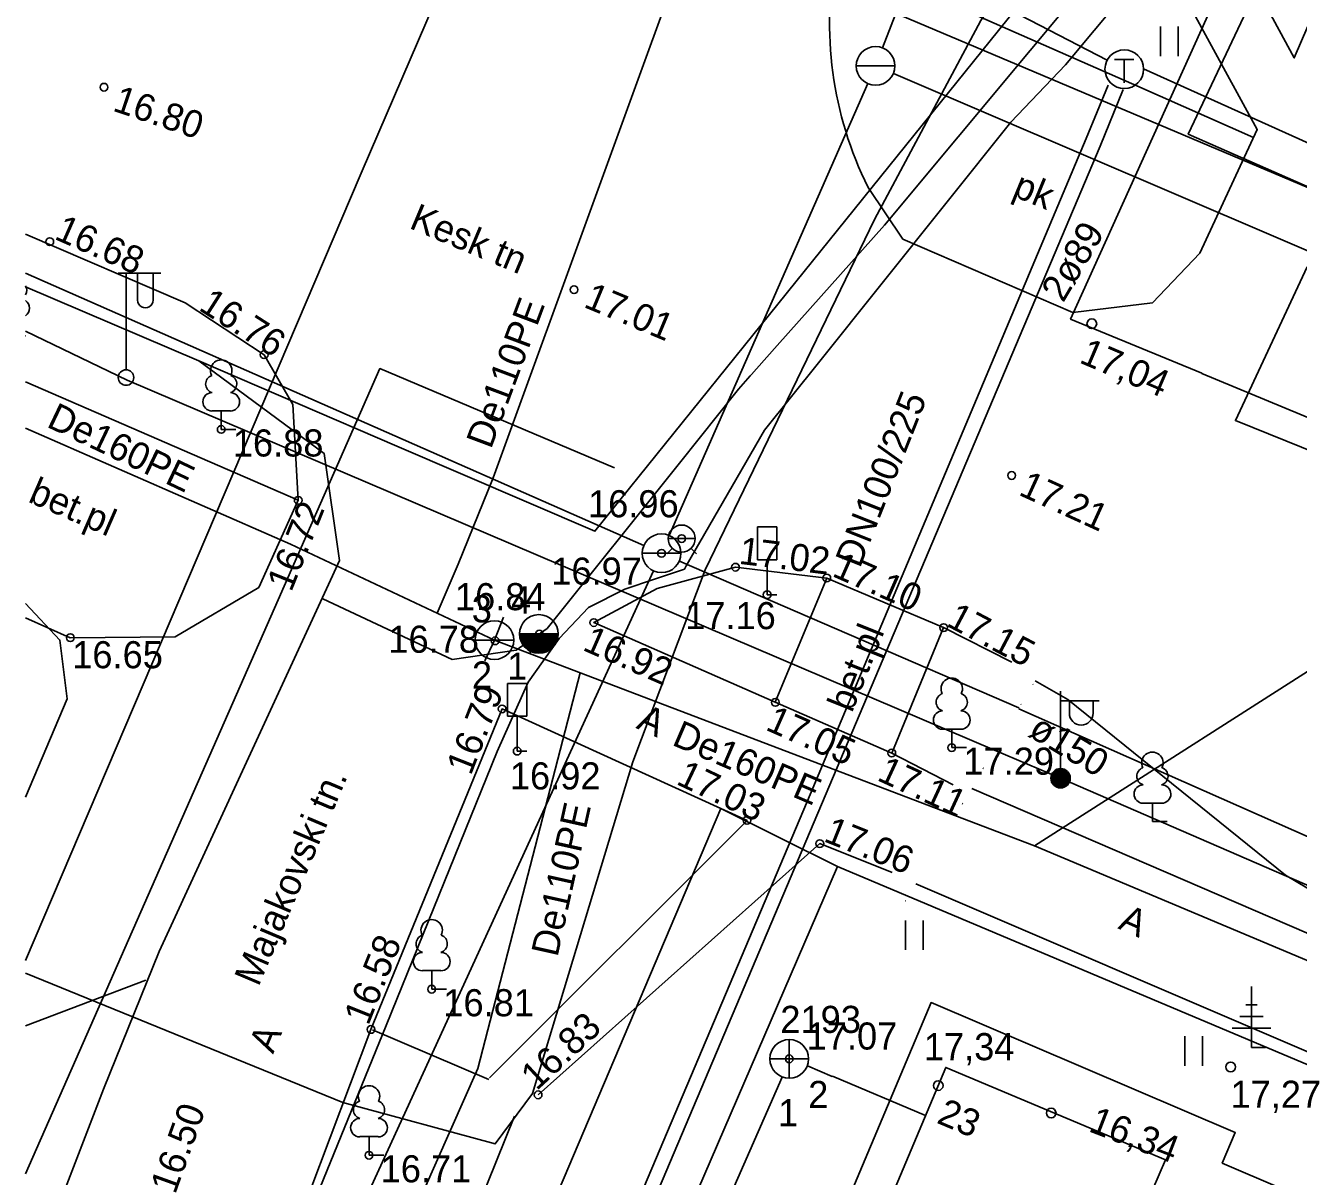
# Model space of a CAD drawing. Extents: x 713497 to 713863, y 6590062 to 6590327.
# Drawn here: x 713496.86 to 713529.76, y 6590263.86 to 6590293.59 of the extents above; entities that cross this region are included whole.
import ezdxf

# ---------------------------------------------------------------- set-up
doc = ezdxf.new("R2010")
doc.units = 0
for name, color, linetype in [('HALJASTUS', 7, 'Continuous'), ('HOONE', 7, 'Continuous'), ('KKAEV', 7, 'Continuous'), ('KORGUS', 7, 'Continuous'), ('KPKAABEL', 7, 'Continuous'), ('KTRASS', 7, 'Continuous'), ('LIIKLUS', 7, 'Continuous'), ('MPKAABEL', 7, 'Continuous'), ('POST', 7, 'Continuous'), ('PUU', 7, 'Continuous'), ('SIKAEV', 7, 'Continuous'), ('SITRASS', 7, 'Continuous'), ('TEE', 7, 'Continuous'), ('TKAEV', 7, 'Continuous'), ('TORU NR', 7, 'Continuous'), ('TTRASS', 7, 'Continuous'), ('VKAEV', 7, 'Continuous'), ('VTRASS', 7, 'Continuous'), ('Слой 1', 7, 'Continuous')]:
    doc.layers.add(name, color=color, linetype=linetype)

msp = doc.modelspace()

# ---------------------------------------------------------------- linework, layer by layer
at = {"layer": 'HALJASTUS'}
for p, q in [((713526.192, 6590293.566), (713526.192, 6590292.805)), ((713526.647, 6590293.566), (713526.647, 6590292.805)), ((713519.603, 6590270.476), (713519.603, 6590269.715)), ((713520.058, 6590270.476), (713520.058, 6590269.715)), ((713526.826, 6590267.486), (713526.826, 6590266.724)), ((713527.281, 6590267.486), (713527.281, 6590266.724))]:
    msp.add_line(p, q, dxfattribs=at)
msp.add_lwpolyline([(713521.623, 6590274.399), (713521.607, 6590274.406)], dxfattribs=at)
at = {"layer": 'HOONE'}
for points in [[(713505.559, 6590289.839), (713515.06, 6590311.86), (713519.629, 6590322.555)], [(713527.264, 6590284.61), (713523.87, 6590286.01), (713535.98, 6590312.79)], [(713496.861, 6590269.441), (713505.51, 6590289.72), (713505.559, 6590289.839)], [(713527.261, 6590284.603), (713571.838, 6590266.115), (713573.888, 6590266.247), (713614.395, 6590248.483), (713630.517, 6590241.151), (713667.174, 6590224.027), (713666.91, 6590213.67), (713710.13, 6590192.26), (713734.713, 6590179.152)], [(713560.928, 6590245.865), (713562.226, 6590248.956), (713556.488, 6590251.366), (713556.171, 6590250.61), (713545.867, 6590255.029), (713546.422, 6590256.351), (713536.953, 6590260.398), (713536.402, 6590259.089), (713526, 6590263.535), (713526.322, 6590264.289), (713520.645, 6590266.681), (713517.107, 6590258.276)]]:
    msp.add_lwpolyline(points, dxfattribs=at)
at = {"layer": 'KKAEV'}
for p, q in [((713516.6, 6590266.4), (713516.6, 6590267.4)), ((713516.1, 6590266.9), (713517.1, 6590266.9))]:
    msp.add_line(p, q, dxfattribs=at)
msp.add_circle((713516.6, 6590266.9), 0.5, dxfattribs=at)
at = {"layer": 'KORGUS'}
for centre, radius in [((713498.89, 6590292), 0.1), ((713497.49, 6590288.01), 0.1), ((713511.04, 6590286.77), 0.1), ((713524.42, 6590285.89), 0.125), ((713503.03, 6590285.09), 0.1), ((713501.92, 6590283.16), 0.1), ((713522.35, 6590281.97), 0.1), ((713503.91, 6590281.33), 0.1), ((713513.82, 6590280.34), 0.1), ((713513.3, 6590279.96), 0.1), ((713515.21, 6590279.6), 0.1), ((713517.57, 6590279.32), 0.1), ((713516.03, 6590278.89), 0.1), ((713511.55, 6590278.17), 0.1), ((713520.59, 6590278.04), 0.1), ((713498.02, 6590277.78), 0.1), ((713510.14, 6590277.87), 0.1), ((713509, 6590277.7), 0.1), ((713516.24, 6590276.11), 0.1), ((713509.18, 6590275.94), 0.1), ((713509.57, 6590274.85), 0.1), ((713519.25, 6590274.8), 0.1), ((713520.8, 6590274.94), 0.1), ((713515.51, 6590273.06), 0.1), ((713517.39, 6590272.46), 0.1), ((713507.36, 6590268.7), 0.1), ((713505.79, 6590267.66), 0.1), ((713516.6, 6590266.9), 0.1), ((713528.01, 6590266.69), 0.125), ((713520.45, 6590266.21), 0.125), ((713510.11, 6590265.97), 0.1), ((713523.37, 6590265.5), 0.125), ((713505.74, 6590264.41), 0.1)]:
    msp.add_circle(centre, radius, dxfattribs=at)
at = {"layer": 'KPKAABEL'}
msp.add_lwpolyline([(713529.988, 6590287.362), (713528.13, 6590283.39), (713562.908, 6590269.342), (713609.57, 6590248.393), (713642.834, 6590233.164), (713665.543, 6590222.669), (713703.801, 6590203.145), (713710.007, 6590200.019), (713735.256, 6590187.298), (713757.247, 6590176.218), (713786.95, 6590160.25), (713778.485, 6590144.103)], dxfattribs=at)
at = {"layer": 'KTRASS'}
for p, q in [((713517.711, 6590266.44), (713517.07, 6590266.72)), ((713516.42, 6590266.43), (713507.63, 6590246.48))]:
    msp.add_line(p, q, dxfattribs=at)
msp.add_lwpolyline([(713517.716, 6590266.452), (713520.122, 6590265.44)], dxfattribs=at)
at = {"layer": 'LIIKLUS'}
for p, q in [((713515.78, 6590280.64), (713515.78, 6590279.79)), ((713516.28, 6590280.64), (713515.78, 6590280.64)), ((713516.28, 6590280.64), (713516.28, 6590279.79)), ((713516.28, 6590279.79), (713515.78, 6590279.79)), ((713516.03, 6590279.79), (713516.03, 6590278.89)), ((713516.28, 6590278.89), (713516.03, 6590278.89)), ((713509.32, 6590276.6), (713509.32, 6590275.75)), ((713509.82, 6590276.6), (713509.32, 6590276.6)), ((713509.82, 6590276.6), (713509.82, 6590275.75)), ((713509.82, 6590275.75), (713509.32, 6590275.75)), ((713509.57, 6590275.75), (713509.57, 6590274.85)), ((713509.82, 6590274.85), (713509.57, 6590274.85))]:
    msp.add_line(p, q, dxfattribs=at)
at = {"layer": 'MPKAABEL'}
for points in [[(713556.424, 6590327.391), (713556.223, 6590326.664), (713552.132, 6590327.245), (713549.78, 6590326.91), (713545.79, 6590321.14), (713541.662, 6590317.664), (713538.182, 6590313.186), (713528.61, 6590303.11), (713525.635, 6590299.613), (713521.549, 6590293.725), (713518.804, 6590288.58), (713514.43, 6590279.53), (713512.558, 6590274.575), (713509.964, 6590266.002), (713509.002, 6590264.701), (713505.064, 6590265.776), (713496.861, 6590269.111)], [(713531.89, 6590304.492), (713530.4, 6590302.03), (713519.06, 6590288.44), (713516.291, 6590285.326)], [(713515.66, 6590285.591), (713524.88, 6590297.03), (713531.868, 6590304.442)], [(713517.352, 6590284.879), (713522.33, 6590291.1), (713523.74, 6590292.58), (713528.97, 6590298.85), (713530.064, 6590300.386)], [(713496.861, 6590286.847), (713501.34, 6590284.93), (713506.46, 6590282.73), (713511.58, 6590280.53), (713515.657, 6590285.592)], [(713521.905, 6590274.877), (713499.491, 6590284.435), (713496.861, 6590285.699)], [(713516.291, 6590285.326), (713515.29, 6590284.2), (713513.76, 6590282.29), (713510.34, 6590278.02), (713509.54, 6590277.46), (713507.89, 6590277.22), (713504.55, 6590278.78)], [(713496.861, 6590260.884), (713496.98, 6590261.19), (713498.88, 6590266.12), (713500.32, 6590269.67), (713502.73, 6590274.9), (713504.8, 6590279.38), (713504.98, 6590279.77), (713504.58, 6590282.54), (713501.34, 6590284.93)], [(713517.352, 6590284.879), (713515.96, 6590283.14), (713513.94, 6590279.64), (713513.89, 6590279.55), (713513.12, 6590279.29), (713512.35, 6590279.03), (713511.41, 6590278.56), (713510.65, 6590277.76), (713509.85, 6590276.63), (713509.05, 6590274.84), (713506.18, 6590267.76), (713501.78, 6590256.97), (713499.96, 6590252.48), (713497.24, 6590245.7), (713496.861, 6590244.767)], [(713496.861, 6590263.928), (713503.3, 6590278.54), (713506.02, 6590284.73), (713512.08, 6590282.17)], [(713504.55, 6590278.78), (713507.89, 6590277.22), (713509.54, 6590277.46), (713510.34, 6590278.02), (713513.76, 6590282.29), (713515.29, 6590284.2), (713515.59, 6590284.54)], [(713522.597, 6590276.054), (713522.584, 6590276.059)], [(713649.332, 6590187.338), (713640.094, 6590185.585), (713635.77, 6590206.95), (713632.04, 6590224.25), (713630.57, 6590226.81), (713628.65, 6590228.67), (713627.42, 6590229.49), (713598.73, 6590243.21), (713583.058, 6590248.245), (713565.046, 6590256.189), (713523.612, 6590274.149), (713521.905, 6590274.877)], [(713496.861, 6590267.757), (713499.97, 6590268.93)]]:
    msp.add_lwpolyline(points, dxfattribs=at)
at = {"layer": 'POST'}
for p, q in [((713499.26, 6590287.2), (713500.36, 6590287.2)), ((713499.46, 6590287.2), (713499.46, 6590284.7)), ((713499.76, 6590287.2), (713499.76, 6590286.5)), ((713500.16, 6590287.2), (713500.16, 6590286.5)), ((713523.612, 6590274.399), (713523.612, 6590276.399)), ((713523.612, 6590276.149), (713524.612, 6590276.149)), ((713523.839, 6590275.828), (713523.839, 6590276.149)), ((713524.452, 6590275.828), (713524.452, 6590276.149))]:
    msp.add_line(p, q, dxfattribs=at)
for centre, radius in [((713499.46, 6590284.5), 0.2), ((713523.612, 6590274.149), 0.25), ((713523.612, 6590274.149), 0.225), ((713523.612, 6590274.149), 0.2), ((713523.612, 6590274.149), 0.175), ((713523.612, 6590274.149), 0.15), ((713523.612, 6590274.149), 0.125), ((713523.612, 6590274.149), 0.1), ((713523.612, 6590274.149), 0.075), ((713523.612, 6590274.149), 0.05), ((713523.612, 6590274.149), 0.025)]:
    msp.add_circle(centre, radius, dxfattribs=at)
for centre, radius, start, end in [((713499.96, 6590286.5), 0.2, 179.9393, 0.0607), ((713524.145, 6590275.828), 0.306, 180, 0)]:
    msp.add_arc(centre, radius, start, end, dxfattribs=at)
at = {"layer": 'PUU'}
for p, q in [((713496.87, 6590285.58), (713496.861, 6590285.58)), ((713502.16, 6590283.64), (713501.68, 6590283.64)), ((713501.92, 6590283.16), (713501.92, 6590283.64)), ((713502.3, 6590283.16), (713501.92, 6590283.16)), ((713521.04, 6590275.42), (713520.56, 6590275.42)), ((713520.8, 6590274.94), (713520.8, 6590275.42)), ((713521.18, 6590274.94), (713520.8, 6590274.94)), ((713526.226, 6590273.503), (713525.746, 6590273.503)), ((713525.986, 6590273.028), (713525.986, 6590273.503)), ((713526.366, 6590273.028), (713525.986, 6590273.028)), ((713507.6, 6590269.18), (713507.12, 6590269.18)), ((713507.36, 6590268.7), (713507.36, 6590269.18)), ((713507.74, 6590268.7), (713507.36, 6590268.7)), ((713528.547, 6590267.193), (713528.547, 6590268.768)), ((713528.697, 6590268.293), (713528.397, 6590268.293)), ((713528.847, 6590267.993), (713528.247, 6590267.993)), ((713529.047, 6590267.693), (713528.047, 6590267.693)), ((713528.907, 6590267.193), (713528.547, 6590267.193)), ((713505.98, 6590264.89), (713505.5, 6590264.89)), ((713505.74, 6590264.41), (713505.74, 6590264.89)), ((713506.12, 6590264.41), (713505.74, 6590264.41))]:
    msp.add_line(p, q, dxfattribs=at)
for centre, radius, start, end in [((713496.66, 6590286.753), 0.233, 329.9101, 30.0899), ((713496.727, 6590286.292), 0.238, 304.2921, 55.7079), ((713501.92, 6590284.68), 0.277, 332.5799, 207.4201), ((713501.75, 6590284.333), 0.233, 109.0217, 253.1415), ((713502.09, 6590284.333), 0.233, 286.8508, 70.9859), ((713501.683, 6590283.872), 0.238, 90.0016, 269.3953), ((713502.157, 6590283.872), 0.238, 270.6047, 89.9984), ((713520.8, 6590276.46), 0.277, 332.5799, 207.4201), ((713520.63, 6590276.113), 0.233, 109.0217, 253.1415), ((713520.97, 6590276.113), 0.233, 286.8508, 70.9859), ((713520.563, 6590275.652), 0.238, 90.0016, 269.3953), ((713521.037, 6590275.652), 0.238, 270.6047, 89.9984), ((713525.986, 6590274.548), 0.277, 332.5799, 207.4201), ((713525.816, 6590274.201), 0.233, 109.0217, 253.1415), ((713526.157, 6590274.201), 0.233, 286.8508, 70.9859), ((713525.749, 6590273.741), 0.238, 90.0016, 269.3953), ((713526.224, 6590273.741), 0.238, 270.6047, 89.9984), ((713507.36, 6590270.22), 0.277, 332.5799, 207.4201), ((713507.19, 6590269.873), 0.233, 109.0217, 253.1415), ((713507.53, 6590269.873), 0.233, 286.8508, 70.9859), ((713507.123, 6590269.412), 0.238, 90.0016, 269.3953), ((713507.597, 6590269.412), 0.238, 270.6047, 89.9984), ((713505.74, 6590265.93), 0.277, 332.5799, 207.4201), ((713505.57, 6590265.583), 0.233, 109.0217, 253.1415), ((713505.91, 6590265.583), 0.233, 286.8508, 70.9859), ((713505.503, 6590265.122), 0.238, 90.0016, 269.3953), ((713505.977, 6590265.122), 0.238, 270.6047, 89.9984)]:
    msp.add_arc(centre, radius, start, end, dxfattribs=at)
at = {"layer": 'SITRASS'}
for points in [[(713496.861, 6590303.284), (713500.921, 6590301.592), (713518.63, 6590294.21), (713525.943, 6590291.121), (713547.87, 6590281.86), (713577.05, 6590269.06)], [(713496.861, 6590273.664), (713497.94, 6590276.2), (713497.75, 6590277.72), (713496.861, 6590278.662)]]:
    msp.add_lwpolyline(points, dxfattribs=at)
at = {"layer": 'TEE'}
for p, q in [((713516.24, 6590276.11), (713517.57, 6590279.32)), ((713519.25, 6590274.8), (713520.59, 6590278.04)), ((713505.83, 6590267.65), (713508.84, 6590266.37)), ((713509.5, 6590265.42), (713505.67, 6590255.93))]:
    msp.add_line(p, q, dxfattribs=at)
for points in [[(713573.49, 6590310.58), (713571.43, 6590310.51), (713568.73, 6590310.13), (713566.75, 6590309.6), (713565.2, 6590309.33), (713563.34, 6590309.28), (713559.47, 6590309.2), (713550.571, 6590309.122), (713547.007, 6590308.859), (713543.266, 6590308.267), (713539.684, 6590306.737), (713533.203, 6590301.01), (713529.652, 6590292.758), (713524.443, 6590302.359), (713528.272, 6590311.829), (713529.607, 6590315.209), (713534.577, 6590327.391)], [(713528.697, 6590290.905), (713523.614, 6590300.222), (713521.391, 6590293.979)], [(713517.839, 6590295.448), (713524.737, 6590292.406), (713525.581, 6590292.034), (713528.602, 6590290.701), (713528.697, 6590290.905), (713527.21, 6590287.717), (713525.99, 6590286.43), (713523.928, 6590286.179), (713519.539, 6590288.076), (713518.637, 6590289.412)], [(713496.861, 6590288.208), (713500.99, 6590286.43), (713503.03, 6590285.09), (713503.77, 6590283.8), (713503.91, 6590281.33), (713502.89, 6590279.08), (713500.73, 6590277.8), (713498.02, 6590277.78), (713496.861, 6590278.291)], [(713503.91, 6590281.33), (713496.861, 6590284.391)], [(713520.84, 6590273.98), (713519.25, 6590274.8), (713516.24, 6590276.11), (713511.55, 6590278.17), (713513.19, 6590279.05), (713515.21, 6590279.6), (713517.57, 6590279.32), (713520.59, 6590278.04), (713522.35, 6590277.15)], [(713522.892, 6590276.579), (713522.903, 6590276.574)], [(713567.652, 6590257.496), (713558.117, 6590259.202), (713555.243, 6590260.095), (713531.713, 6590270.286), (713529.422, 6590271.644), (713523.797, 6590276.181), (713522.955, 6590276.663)], [(713503.16, 6590260.68), (713505.79, 6590267.66), (713509.18, 6590275.94), (713515.51, 6590273.06), (713508.85, 6590266.41)], [(713521.322, 6590273.886), (713531.345, 6590269.56)], [(713521.087, 6590273.488), (713521.069, 6590273.496)], [(713510.11, 6590265.97), (713517.39, 6590272.46), (713519.26, 6590271.71)], [(713519.87, 6590271.419), (713539.627, 6590262.954)], [(713519.614, 6590270.982), (713519.607, 6590270.985)], [(713536.914, 6590260.306), (713527.79, 6590264.206), (713528.127, 6590264.994), (713520.265, 6590268.354), (713516.169, 6590258.625)]]:
    msp.add_lwpolyline(points, dxfattribs=at)
msp.add_arc((713527.16, 6590293.653), 9.519, 168.9353, 206.4518, dxfattribs=at)
at = {"layer": 'TKAEV'}
for p, q in [((713525.009, 6590292.716), (713525.509, 6590292.716)), ((713525.259, 6590292.116), (713525.259, 6590292.716))]:
    msp.add_line(p, q, dxfattribs=at)
msp.add_circle((713525.259, 6590292.466), 0.5, dxfattribs=at)
at = {"layer": 'TTRASS'}
for points in [[(713519.57, 6590295.42), (713524.815, 6590292.696)], [(713579.86, 6590268.18), (713569.16, 6590273.06), (713552.4, 6590280.47), (713525.759, 6590292.472)], [(713524.838, 6590292.055), (713524.274, 6590290.678), (713517.074, 6590273.563), (713509.525, 6590255.749), (713509.26, 6590255.635), (713504.886, 6590257.539), (713504.59, 6590257.406), (713499.908, 6590246.416), (713496.861, 6590238.236)], [(713525.234, 6590291.937), (713524.637, 6590290.479), (713517.341, 6590273.249), (713509.7, 6590255.207), (713509.387, 6590255.185), (713505.154, 6590257.086), (713504.889, 6590256.981), (713500.184, 6590245.949), (713496.861, 6590237.277)]]:
    msp.add_lwpolyline(points, dxfattribs=at)
at = {"layer": 'VKAEV'}
for p, q in [((713518.331, 6590292.55), (713519.331, 6590292.55)), ((713513.47, 6590280.34), (713514.17, 6590280.34)), ((713512.8, 6590279.96), (713513.8, 6590279.96)), ((713513.58, 6590280.09), (713513.44, 6590279.95)), ((713514.06, 6590280.09), (713514.2, 6590279.95)), ((713509.629, 6590277.876), (713510.629, 6590277.876)), ((713508.482, 6590277.717), (713509.482, 6590277.717))]:
    msp.add_line(p, q, dxfattribs=at)
for centre, radius in [((713518.831, 6590292.55), 0.5), ((713513.3, 6590279.96), 0.5), ((713513.82, 6590280.34), 0.35), ((713508.982, 6590277.717), 0.5), ((713510.129, 6590277.876), 0.5)]:
    msp.add_circle(centre, radius, dxfattribs=at)
for radius in [0.483, 0.468, 0.45, 0.435, 0.418, 0.403, 0.386, 0.371, 0.354, 0.339, 0.321, 0.306, 0.289, 0.274, 0.257, 0.242, 0.224, 0.209, 0.192, 0.177, 0.16, 0.145, 0.127, 0.112, 0.0951, 0.0801, 0.0628, 0.0478, 0.0328, 0.0178]:
    msp.add_arc((713510.129, 6590277.876), radius, 180, 0, dxfattribs=at)
at = {"layer": 'VTRASS'}
for p, q in [((713508.982, 6590277.717), (713509.219, 6590278.314)), ((713510.13, 6590277.873), (713509.894, 6590277.37)), ((713508.982, 6590277.717), (713508.734, 6590277.182))]:
    msp.add_line(p, q, dxfattribs=at)
for points in [[(713507.497, 6590278.416), (713508.047, 6590279.681), (713508.945, 6590281.911), (713514.443, 6590297.018), (713518.94, 6590309.607), (713514.735, 6590311.275), (713514.6, 6590311.326)], [(713519.012, 6590293.016), (713523.308, 6590304.097)], [(713541.27, 6590282.95), (713519.291, 6590292.353)], [(713513.5, 6590280.42), (713518.631, 6590292.092)], [(713496.861, 6590287.195), (713512.84, 6590280.16)], [(713632.54, 6590225.141), (713631.644, 6590225.667), (713613.144, 6590233.236), (713600.179, 6590239.452), (713599.949, 6590239.514), (713585.185, 6590245.627), (713571.869, 6590251.118), (713555.451, 6590258.762), (713536.955, 6590266.515), (713522.936, 6590272.405), (713508.982, 6590277.717), (713503.707, 6590280.197), (713496.861, 6590283.191)], [(713522.936, 6590272.405), (713531.544, 6590277.896), (713539.884, 6590282.936), (713540.42, 6590283.329)], [(713513.09, 6590279.51), (713503.71, 6590259.06)], [(713522.545, 6590275.965), (713522.532, 6590275.971), (713513.76, 6590279.76)], [(713496.861, 6590237.995), (713500.379, 6590246.785), (713503.942, 6590256.254), (713508.554, 6590266.652), (713511.201, 6590276.873)], [(713522.533, 6590275.945), (713575.803, 6590252.382)]]:
    msp.add_lwpolyline(points, dxfattribs=at)
at = {"layer": 'Слой 1'}
for points in [[(713534.6, 6590307.05), (713570.51, 6590314.26), (713572.89, 6590321.37), (713595.83, 6590312.09), (713577.56, 6590268.53), (713526.91, 6590290.79)], [(713514.83, 6590273.37), (713517.85, 6590271.87), (713503.89, 6590239.55), (713548.37, 6590220.95), (713544.59, 6590212), (713497.4, 6590232.32)], [(713517.85, 6590271.87), (713564.88, 6590252.05), (713555.24, 6590227.9), (713551.71, 6590229.31), (713548.37, 6590220.95), (713503.89, 6590239.55)]]:
    msp.add_lwpolyline(points, close=True, dxfattribs=at)

# ---------------------------------------------------------------- texts
at = {"layer": 'HOONE'}
msp.add_text('23', height=0.7, rotation=337.1617, dxfattribs=at).set_placement((713520.383, 6590265.256))
at = {"layer": 'KORGUS'}
for s, rotation, p in [('16.80', 341.2734, (713499.09, 6590291.4)), ('16.68', 336.1823, (713497.58, 6590288.09)), ('16.76', 327.4017, (713501.31, 6590286.26)), ('17.01', 337.3917, (713511.26, 6590286.33)), ('17,04', 336.8452, (713524.067, 6590284.897)), ('17.21', 335.5217, (713522.5, 6590281.48)), ('16.72', 68.0861, (713503.73, 6590278.94)), ('17.02', 353.0437, (713515.28, 6590279.69)), ('17.10', 336.2393, (713517.68, 6590279.38)), ('17.15', 332.1917, (713520.63, 6590278.1)), ('16.92', 336.3503, (713511.23, 6590277.47)), ('16.79', 68.4998, (713508.37, 6590274.2)), ('17.05', 336.0794, (713515.96, 6590275.41)), ('17.03', 334.6477, (713513.65, 6590274.01)), ('17.11', 335.2064, (713518.84, 6590274.11)), ('17.06', 338.1002, (713517.46, 6590272.53)), ('16.58', 68.1986, (713505.72, 6590267.74)), ('16.83', 42.8094, (713510.07, 6590266.06)), ('16.50', 70.23, (713500.73, 6590263.38)), ('16,34', 338.9477, (713524.309, 6590265.037))]:
    msp.add_text(s, height=0.7, rotation=rotation, dxfattribs=at).set_placement(p)
for s, p in [('16.88', (713502.22, 6590282.46)), ('16.96', (713511.4, 6590280.89)), ('16.97', (713510.45, 6590279.15)), ('16.84', (713507.96, 6590278.49)), ('17.16', (713513.91, 6590278)), ('16.78', (713506.24, 6590277.39)), ('16.65', (713498.07, 6590276.99)), ('17.29', (713521.1, 6590274.24)), ('16.92', (713509.38, 6590273.86)), ('16.81', (713507.66, 6590268)), ('17.07', (713517.05, 6590267.14)), ('17,34', (713520.078, 6590266.865)), ('17,27', (713528.003, 6590265.635)), ('16.71', (713506.04, 6590263.71))]:
    msp.add_text(s, height=0.7, dxfattribs=at).set_placement(p)
at = {"layer": 'SIKAEV'}
msp.add_text('2193', height=0.7, dxfattribs=at).set_placement((713516.37, 6590267.57))
at = {"layer": 'TEE'}
for s, rotation, p in [('pk', 337.6051, (713522.34, 6590289.201)), ('Kesk tn', 337.2064, (713506.75, 6590288.37)), ('bet.pl', 336.4621, (713496.9, 6590281.3)), ('bet.pl', 68.1883, (713518.22, 6590275.82)), ('A', 336.0487, (713512.62, 6590275.45)), ('Majakovski tn.', 67.0362, (713502.883, 6590268.745)), ('A', 336.0487, (713525.073, 6590270.275)), ('A', 67.3693, (713503.26, 6590267.01))]:
    msp.add_text(s, height=0.7, rotation=rotation, dxfattribs=at).set_placement(p)
at = {"layer": 'TORU NR'}
for s, rotation, p in [('2ø89', 59.3381, (713523.679, 6590286.413)), ('ø150', 328.9855, (713522.744, 6590275.257))]:
    msp.add_text(s, height=0.7, rotation=rotation, dxfattribs=at).set_placement(p)
for s, p in [('3', (713508.395, 6590278.175)), ('4', (713509.411, 6590278.403)), ('2', (713508.399, 6590276.466)), ('1', (713509.309, 6590276.693)), ('2', (713517.09, 6590265.63)), ('1', (713516.31, 6590265.16))]:
    msp.add_text(s, height=0.7, dxfattribs=at).set_placement(p)
at = {"layer": 'TTRASS'}
msp.add_text('DN100/225', height=0.7, rotation=68.4288, dxfattribs=at).set_placement((713518.424, 6590279.555))
at = {"layer": 'VTRASS'}
for s, rotation, p in [('De110PE', 69.461, (713508.89, 6590282.63)), ('De160PE', 334.5289, (713497.38, 6590283.24)), ('De160PE', 336.7857, (713513.54, 6590275.02)), ('De110PE', 77.4657, (713510.61, 6590269.51))]:
    msp.add_text(s, height=0.7, rotation=rotation, dxfattribs=at).set_placement(p)

doc.saveas('drawing.dxf')
